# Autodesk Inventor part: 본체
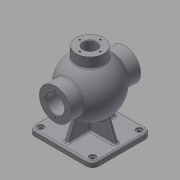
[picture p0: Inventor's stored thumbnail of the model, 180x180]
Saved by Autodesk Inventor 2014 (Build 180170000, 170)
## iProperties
Created: 2015-10
Part Number: 본체
Material: Generic
Document SubType Name: Modeling
Designer: youjin14
Density: 1 g/cm^3
Appearance: Default
Author: youjin14
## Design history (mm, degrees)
sketch "Sketch1"
  geometry: L1 (-50.5, -57.5)-(50.5, -57.5); L2 (62.5, -45.5)-(62.5, 45.5); L3 (50.5, 57.5)-(-50.5, 57.5); L4 (-62.5, 45.5)-(-62.5, -45.5); L5 (-62.5, -57.5)-(62.5, 57.5); L6 (62.5, -57.5)-(-62.5, 57.5); A1 r 12 centre (-50.5, 45.5) between (-50.5, 57.5) and (-62.5, 45.5); A2 r 12 centre (-50.5, -45.5) between (-62.5, -45.5) and (-50.5, -57.5); A3 r 12 centre (50.5, -45.5) between (50.5, -57.5) and (62.5, -45.5); A4 r 12 centre (50.5, 45.5) between (62.5, 45.5) and (50.5, 57.5); 1 further point
  constraints: 12 end point, 8 point on circle, 8 point on line, 8 tangent, 4 centre point, 3 equal radius, 2 midpoint, 2 parallel, 1 horizontal, 1 perpendicular
  dimensions: "d0" = 125 distance of L6.end L5.end; "d1" = 115 distance of L5.end L6.start; "d2" = 12 radius of A1
extrude "Extrusion1" new body sketch "Sketch1" distance "d3" = 10; taper "d4" = 0 deg
sketch "Sketch2"
  geometry: A1 r 12 centre (-50.5, 45.5) between (-50.5, 57.5) and (-62.5, 45.5) reference; A2 r 12 centre (-50.5, -45.5) between (-62.5, -45.5) and (-50.5, -57.5) reference; A3 r 12 centre (50.5, -45.5) between (50.5, -57.5) and (62.5, -45.5) reference; A4 r 12 centre (50.5, 45.5) between (62.5, 45.5) and (50.5, 57.5) reference; 5 further points
  constraints: 4 coincident
  dimensions: "d5" = 101 distance of A4.centre A1.centre (derived); "d6" = 91 distance of A3.centre A4.centre (derived)
hole "Hole1" sketch "Sketch2" at (-50.5, 45.5), (50.5, 45.5), (-50.5, -45.5), (50.5, -45.5) diameter "d7" = 8; stored, may be unused: countersink angle "d11" = 90 deg, drill point angle "d13" = 0 deg; dims "d8" = 6, "d9" = 12, "d10" = 3, "d12" = 10
fillet "Fillet1" dims "d14" = 3
sketch "Sketch3"
  geometry: 2 further points
  constraints: 1 vertical alignment
  dimensions: "d15" = 85 distance of point (0, 0) point (0, 85)
sketch "Sketch4"
  geometry: L1 (36.862, 123.082)-(-36.862, 46.918); A1 r 53 centre (0, 85) between (36.862, 123.082) and (-36.862, 46.918); 1 further point
  constraints: 2 end point, 2 point on circle, 1 centre point, 1 midpoint
  dimensions: "d16" = 53 radius of A1
revolve "Revolution1" sketch "Sketch4" stored, may be unused: angle "d17" = 90 deg
sketch "Sketch5"
  geometry: L1 (-4, -4)-(4, -4); L2 (4, -4)-(4, 4); L3 (4, 4)-(-4, 4); L4 (-4, 4)-(-4, -4); L5 (-4, -4)-(4, 4); L6 (4, -4)-(-4, 4); 1 further point
  constraints: 12 end point, 2 midpoint, 2 parallel, 1 horizontal, 1 perpendicular
  dimensions: "d18" = 8 distance of L3.end L2.end; "d19" = 8 distance of L2.end L1.end
extrude "Extrusion2" join sketch "Sketch5" stored distance "d20" = 10; taper "d21" = 0 deg
sketch "Sketch6"
  geometry: L1 (-4, 10)-(-4, 32.303) reference; L2 (-50.5, 10)-(50.5, 10) reference; L3 (-56.5, 10)-(-44.5, 10) reference; L4 (44.5, 10)-(56.5, 10) reference; L5 (52.5, 10)-(37.379, 47.426); L6 (62.5, 0)-(62.5, 7) reference; L7 (-52.5, 10)-(-37.379, 47.426); L8 (-62.5, 0)-(-62.5, 7) reference; A1 r 53 centre (0, 85) between (4, 32.151) and (-4, 32.151) reference; 1 further point
  constraints: 4 end point, 2 point on circle, 2 point on line
  dimensions: "d22" = 10 distance from line of L6 L5.start; "d23" = 10 distance from line of L8 L7.start; "d24" = 22 deg angle of L7 L8; "d25" = 22 deg angle of L6 L5
feature "Rib1" dims "d26" = 1, "d27" = 8, "d28" = 0, "d29" = 0, "d30" = 1, "d31" = 1
feature "Rib2" dims "d32" = 1, "d33" = 8, "d34" = 0, "d35" = 0, "d36" = 1, "d37" = 1
sketch "Sketch7"
  geometry: L1 (-4, 10)-(-4, 47.578) reference; L2 (-45.5, 10)-(45.5, 10) reference; L3 (-51.5, 10)-(-39.5, 10) reference; L4 (39.5, 10)-(51.5, 10) reference; L5 (-54.5, 10)-(-45.5, 10) reference; L6 (45.5, 10)-(54.5, 10) reference; L7 (-47.5, 10)-(-33.719, 44.109); L8 (47.5, 10)-(33.719, 44.109); L9 (57.5, 0)-(57.5, 7) reference; L10 (-57.5, 0)-(-57.5, 7) reference; A1 r 53 centre (0, 85) between (4, 32.151) and (-4, 32.151) reference; 1 further point
  constraints: 4 end point, 2 point on circle, 2 point on line
  dimensions: "d38" = 10 distance from line of L9 L8.start; "d39" = 10 distance from line of L10 L7.start; "d40" = 22 deg angle of L10 L7; "d41" = 22 deg angle of L9 L8
feature "Rib3" dims "d42" = 1, "d43" = 8, "d44" = 0, "d45" = 0, "d46" = 1, "d47" = 1
feature "Rib4" dims "d48" = 1, "d49" = 8, "d50" = 0, "d51" = 0, "d52" = 1, "d53" = 1
sketch "Sketch8"
  geometry: C1 r 31 at (0, 85); 1 further point
  constraints: 1 centre point, 1 vertical alignment
  dimensions: "d54" = 62 diameter of C1; "d55" = 85 distance of point (0, 0) C1.centre
extrude "Extrusion3" join sketch "Sketch8" stored distance "d56" = 136; taper "d57" = 0 deg
sketch "Sketch9"
  geometry: L1 (42.475, 91.701)-(-42.475, 78.299); A1 r 43 centre (0, 85) between (42.475, 91.701) and (-42.475, 78.299); 1 further point
  constraints: 2 end point, 2 point on circle, 1 centre point, 1 midpoint
  dimensions: "d58" = 43 radius of A1
revolve "Revolution2" sketch "Sketch9" stored, may be unused: angle "d59" = 90 deg
sketch "Sketch10"
  geometry: C1 r 31 at (0, 0) reference; C2 r 17.5 at (0, 0); 1 further point
  constraints: 1 centre point, 1 coincident
  dimensions: "d60" = 35 diameter of C2
extrude "Extrusion4" cut sketch "Sketch10" stored distance "d61" = 136; taper "d62" = 0 deg
workplane "Work Plane1"
sketch "Sketch11"
  geometry: C1 r 27 at (0, 0); 1 further point
  constraints: 1 centre point, 1 coincident
  dimensions: "d64" = 54 diameter of C1
extrude "Extrusion5" join sketch "Sketch11" stored distance "d65" = 136; taper "d66" = 0 deg
sketch "Sketch12"
  geometry: C1 r 27 at (0, 0) reference; C2 r 13 at (0, 0)
  constraints: 1 centre point, 1 coincident
  dimensions: "d67" = 26 diameter of C2
extrude "Extrusion6" cut sketch "Sketch12" stored distance "d68" = 136; taper "d69" = 0 deg
workplane "Work Plane2"
sketch "Sketch13"
  geometry: L1 (45.5, -150)-(-45.5, -150) reference; L2 (-27, -19.393)-(27, -19.393) reference; L3 (-27, 0)-(27, 0) reference; 3 further points
  constraints: 1 midpoint, 1 vertical alignment, 1 other
  dimensions: "d70" = 10 distance from line of L3 point (0, -10)
emboss "Emboss1" sketch "Sketch13" dims "d0" = 125, "d1" = 115, "d2" = 12, "d71" = 0.5, "d72" = 0
sketch "Sketch14"
  geometry: C1 r 17.5 at (0, 0) reference; C2 r 31 at (0, 0) reference; A1 r 22.5 centre (0, 0) between (0, 22.5) and (-22.5, 0); 3 further points
  constraints: 4 point on circle, 2 horizontal alignment, 2 vertical alignment, 1 centre point, 1 coincident
  dimensions: "d73" = 45 diameter of A1
hole "Hole2" sketch "Sketch14" at (0, 22.5), (0, -22.5), (22.5, 0), (-22.5, 0) diameter "d74" = 3.242; stored, may be unused: countersink angle "d78" = 90 deg, drill point angle "d80" = 118 deg; dims "d75" = 12, "d76" = 12, "d77" = 3, "d79" = 15
sketch "Sketch15"
  geometry: C1 r 17.5 at (0, 0) reference; C2 r 31 at (0, 0) reference; A1 r 24 centre (0, 0) between (0, 24) and (-24, 0); 3 further points
  constraints: 4 point on circle, 2 horizontal alignment, 2 vertical alignment, 1 centre point, 1 coincident
  dimensions: "d81" = 48 diameter of A1
hole "Hole3" sketch "Sketch15" at (0, 24), (0, -24), (-24, 0), (24, 0) diameter "d82" = 3.242; stored, may be unused: countersink angle "d86" = 90 deg, drill point angle "d88" = 118 deg; dims "d83" = 16, "d84" = 12, "d85" = 3, "d87" = 19
sketch "Sketch16"
  geometry: C1 r 13 at (0, 0) reference; C2 r 27 at (0, 0) reference; A1 r 20 centre (0, 0) between (0, 20) and (-20, 0); 2 further points
  constraints: 4 point on circle, 2 horizontal alignment, 2 vertical alignment, 1 centre point, 1 coincident
  dimensions: "d89" = 40 diameter of A1
hole "Hole4" sketch "Sketch16" at (0, 20), (0, -20), (-20, 0), (20, 0) diameter "d90" = 3.242; stored, may be unused: countersink angle "d94" = 90 deg, drill point angle "d96" = 118 deg; dims "d91" = 9, "d92" = 12, "d93" = 3, "d95" = 11
workplane "Work Plane3"
sketch "Sketch17"
  geometry: C1 r 17.5 at (0, 85) reference; C2 r 18.5 at (0, 85); 1 further point
  constraints: 1 centre point, 1 coincident
  dimensions: "d98" = 37 diameter of C2
extrude "Extrusion7" cut sketch "Sketch17" distance "d99" = 1.75; taper "d100" = 0 deg
chamfer "Chamfer1" distance "d101" = 1; stored, may be unused: second distance "d102" = 2, angle "d103" = 45 deg
fillet "Fillet2" dims "d104" = 3
fillet "Fillet3" dims "d105" = 3
fillet "Fillet4" dims "d106" = 3
body "Solid1"
node "Projected Loop1"
other parameters: "d97" = -52
